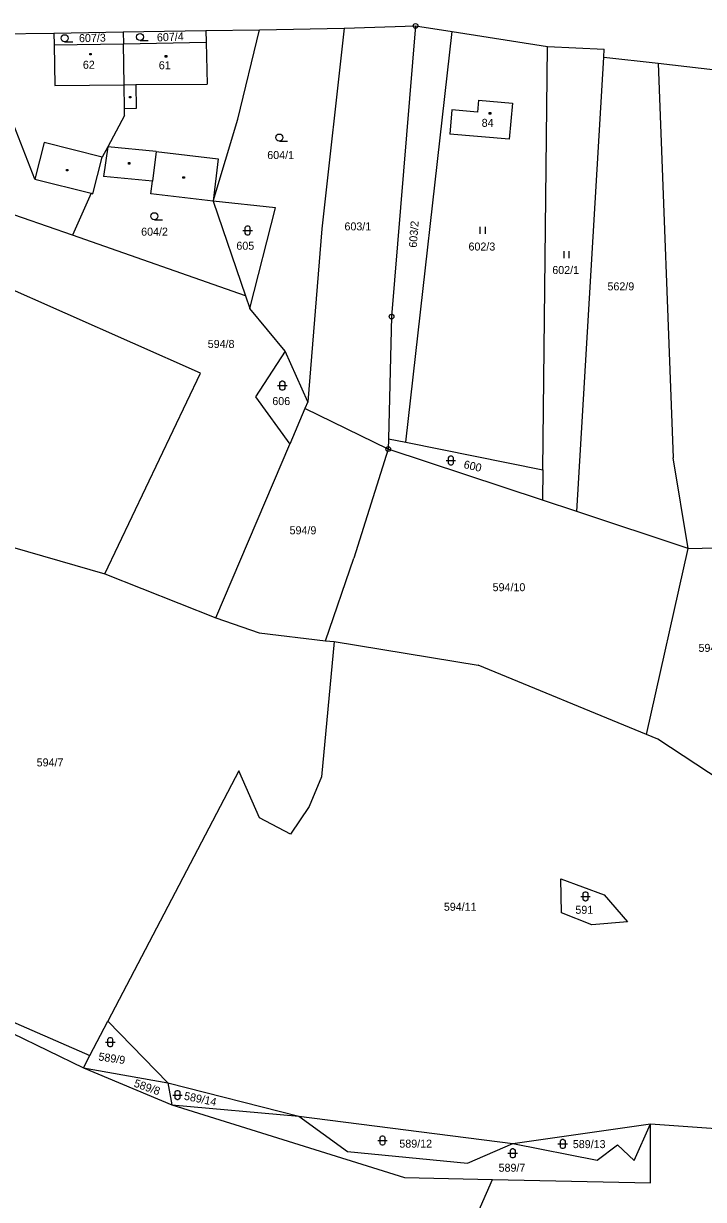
# Model space of a CAD drawing. Extents: x -791032 to -787751, y -1106872 to -1104403.
# Drawn here: x -789077.2 to -788932.6, y -1105471.5 to -1105221.6 of the extents above; entities that cross this region are included whole.
import ezdxf

# ---------------------------------------------------------------- set-up
doc = ezdxf.new("R2010")
doc.units = 0
for name, color, linetype in [('Vrstva 1', 7, 'Continuous'), ('Vrstva 14', 7, 'Continuous'), ('Vrstva 15', 7, 'Continuous'), ('Vrstva 2', 7, 'Continuous'), ('Vrstva 23', 7, 'Continuous'), ('Vrstva 25', 7, 'Continuous'), ('Vrstva 28', 7, 'Continuous')]:
    doc.layers.add(name, color=color, linetype=linetype)

msp = doc.modelspace()

# ---------------------------------------------------------------- linework, layer by layer
at = {"layer": 'Vrstva 1'}
for p, q in [((-789055.97, -1105223.43), (-789038.4, -1105223.14)), ((-789038.4, -1105223.14), (-789027.01, -1105222.95)), ((-789038.4, -1105223.14), (-789038.34, -1105225.61)), ((-789031.62, -1105241.98), (-789027.01, -1105222.95)), ((-789027.01, -1105222.95), (-789008.99, -1105222.66)), ((-789008.99, -1105222.66), (-789013.78, -1105265.28)), ((-789008.99, -1105222.66), (-788993.84, -1105222.14)), ((-788993.84, -1105222.14), (-788998.94, -1105283.9)), ((-788995.93, -1105310.61), (-788986.07, -1105223.35)), ((-788993.84, -1105222.14), (-788986.07, -1105223.35)), ((-788986.07, -1105223.35), (-788965.77, -1105226.5)), ((-789086.8, -1105223.93), (-789070.73, -1105223.67)), ((-789074.73, -1105254.68), (-789086.8, -1105223.93)), ((-789070.73, -1105223.67), (-789055.97, -1105223.43)), ((-789070.73, -1105223.67), (-789070.67, -1105226.2)), ((-789055.97, -1105223.43), (-789055.93, -1105225.93)), ((-789055.93, -1105225.93), (-789038.34, -1105225.61)), ((-789070.67, -1105226.2), (-789055.93, -1105225.93)), ((-789055.78, -1105234.64), (-789055.93, -1105225.93)), ((-788966.77, -1105316.48), (-788965.77, -1105226.5)), ((-788965.77, -1105226.5), (-788953.75, -1105227.08)), ((-788953.85, -1105228.78), (-788953.75, -1105227.08)), ((-788959.53, -1105325.34), (-788953.85, -1105228.78)), ((-788953.85, -1105228.78), (-788942.24, -1105230.09)), ((-788942.24, -1105230.09), (-788916.68, -1105232.99)), ((-788942.24, -1105230.09), (-788939.08, -1105313.94)), ((-789055.68, -1105239.76), (-789055.78, -1105234.64)), ((-788980.45, -1105237.95), (-788980.65, -1105240.44)), ((-788980.45, -1105237.95), (-788973.24, -1105238.59)), ((-789055.66, -1105241.15), (-789055.68, -1105239.76)), ((-788986.14, -1105240), (-788986.55, -1105245.18)), ((-788980.65, -1105240.44), (-788986.14, -1105240)), ((-788973.24, -1105238.59), (-788973.95, -1105246.19)), ((-789055.66, -1105241.15), (-789059.25, -1105247.81)), ((-789036.84, -1105259.37), (-789031.62, -1105241.98)), ((-788973.95, -1105246.19), (-788986.55, -1105245.18)), ((-789059.25, -1105247.81), (-789060.45, -1105250.04)), ((-789059.25, -1105247.81), (-789060.12, -1105254.11)), ((-789062.42, -1105257.8), (-789060.45, -1105250.04)), ((-789066.71, -1105266.61), (-789099.4, -1105255.27)), ((-789074.73, -1105254.68), (-789062.81, -1105257.7)), ((-789049.76, -1105255.16), (-789060.12, -1105254.11)), ((-789050.11, -1105257.8), (-789049.76, -1105255.16)), ((-789062.81, -1105257.7), (-789066.71, -1105266.61)), ((-789062.81, -1105257.7), (-789062.42, -1105257.8)), ((-789036.84, -1105259.37), (-789050.11, -1105257.8)), ((-789023.57, -1105260.83), (-789036.84, -1105259.37)), ((-789036.84, -1105259.37), (-789029.97, -1105279.46)), ((-789029.03, -1105282.2), (-789023.57, -1105260.83)), ((-789039.51, -1105295.94), (-789114.21, -1105262.89)), ((-789013.78, -1105265.28), (-789016.75, -1105302.03)), ((-789029.97, -1105279.46), (-789066.71, -1105266.61)), ((-789029.97, -1105279.46), (-789029.03, -1105282.2)), ((-789021.57, -1105291.22), (-789029.03, -1105282.2)), ((-788998.94, -1105283.9), (-788999.59, -1105309.87)), ((-789021.57, -1105291.22), (-789027.86, -1105300.92)), ((-789016.75, -1105302.03), (-789021.57, -1105291.22)), ((-789059.86, -1105338.55), (-789039.51, -1105295.94)), ((-789027.86, -1105300.92), (-789020.57, -1105311)), ((-789016.75, -1105302.03), (-789017.35, -1105303.43)), ((-789017.35, -1105303.43), (-789020.57, -1105311)), ((-788999.64, -1105312.04), (-789017.35, -1105303.43)), ((-788999.59, -1105309.87), (-788999.64, -1105312.04)), ((-788999.59, -1105309.87), (-788995.93, -1105310.61)), ((-788995.93, -1105310.61), (-788966.77, -1105316.48)), ((-789036.27, -1105347.9), (-789020.57, -1105311)), ((-788999.64, -1105312.04), (-789006.97, -1105335.19)), ((-788966.84, -1105322.92), (-788999.64, -1105312.04)), ((-788935.87, -1105333.19), (-788939.08, -1105313.94)), ((-788966.77, -1105316.48), (-788966.84, -1105322.92)), ((-788959.53, -1105325.34), (-788966.84, -1105322.92)), ((-788935.87, -1105333.19), (-788959.53, -1105325.34)), ((-789091.87, -1105329.34), (-789059.86, -1105338.55)), ((-788944.74, -1105372.67), (-788935.87, -1105333.19)), ((-788935.87, -1105333.19), (-788918.93, -1105332.67)), ((-789012.95, -1105352.75), (-789006.97, -1105335.19)), ((-789059.86, -1105338.55), (-789036.27, -1105347.9)), ((-789036.27, -1105347.9), (-789027.04, -1105351.11)), ((-789027.04, -1105351.11), (-789012.95, -1105352.75)), ((-789011.14, -1105352.96), (-789013.82, -1105381.68)), ((-789012.95, -1105352.75), (-789011.14, -1105352.96)), ((-789011.14, -1105352.96), (-788980.56, -1105357.96)), ((-788944.74, -1105372.67), (-788980.56, -1105357.96)), ((-788942.31, -1105373.67), (-788944.74, -1105372.67)), ((-788928.91, -1105382.54), (-788942.31, -1105373.67)), ((-789031.41, -1105380.38), (-789059.26, -1105433.59)), ((-789027, -1105390.37), (-789031.41, -1105380.38)), ((-789013.82, -1105381.68), (-789016.43, -1105387.95)), ((-789016.43, -1105387.95), (-789020.4, -1105393.85)), ((-789020.4, -1105393.85), (-789027, -1105390.37)), ((-788962.94, -1105403.36), (-788953.73, -1105406.76)), ((-788962.84, -1105410.54), (-788962.94, -1105403.36)), ((-788953.73, -1105406.76), (-788948.8, -1105412.45)), ((-788956.38, -1105413.14), (-788962.84, -1105410.54)), ((-788948.8, -1105412.45), (-788956.38, -1105413.14)), ((-789092.69, -1105427.98), (-789063.07, -1105440.87)), ((-789063.07, -1105440.87), (-789059.26, -1105433.59)), ((-789059.26, -1105433.59), (-789046.46, -1105446.71)), ((-789079.58, -1105436.15), (-789064.43, -1105443.48)), ((-789064.43, -1105443.48), (-789063.07, -1105440.87)), ((-789064.43, -1105443.48), (-789045.62, -1105451.38)), ((-789064.43, -1105443.48), (-789046.46, -1105446.71)), ((-789046.46, -1105446.71), (-789045.62, -1105451.38)), ((-789046.46, -1105446.71), (-789018.61, -1105453.78)), ((-789045.62, -1105451.38), (-788996.21, -1105466.8)), ((-789045.62, -1105451.38), (-789018.61, -1105453.78)), ((-789018.61, -1105453.78), (-789008.3, -1105461.27)), ((-789018.61, -1105453.78), (-788973.19, -1105459.55)), ((-788973.19, -1105459.55), (-788943.93, -1105455.42)), ((-788947.34, -1105463.15), (-788943.93, -1105455.42)), ((-788943.93, -1105455.42), (-788924.79, -1105456.74)), ((-788943.91, -1105467.9), (-788943.93, -1105455.42)), ((-788982.77, -1105463.78), (-788973.19, -1105459.55)), ((-788973.19, -1105459.55), (-788955.21, -1105463.09)), ((-788955.21, -1105463.09), (-788950.91, -1105459.82)), ((-788950.91, -1105459.82), (-788947.34, -1105463.15)), ((-789008.3, -1105461.27), (-788982.77, -1105463.78)), ((-788996.21, -1105466.8), (-788977.5, -1105467.19)), ((-788983.32, -1105480.53), (-788977.5, -1105467.19)), ((-788977.5, -1105467.19), (-788943.91, -1105467.9))]:
    msp.add_line(p, q, dxfattribs=at)
at = {"layer": 'Vrstva 2'}
for p, q in [((-789038.34, -1105225.61), (-789038.12, -1105234.5)), ((-789070.67, -1105226.2), (-789070.47, -1105234.79)), ((-789070.47, -1105234.79), (-789055.78, -1105234.64)), ((-789055.78, -1105234.64), (-789053.27, -1105234.59)), ((-789053.27, -1105234.59), (-789038.12, -1105234.5)), ((-789053.27, -1105234.59), (-789053.18, -1105239.71)), ((-789053.18, -1105239.71), (-789055.68, -1105239.76)), ((-789072.76, -1105246.92), (-789074.73, -1105254.68)), ((-789060.45, -1105250.04), (-789072.76, -1105246.92)), ((-789048.95, -1105248.85), (-789059.25, -1105247.81)), ((-789048.95, -1105248.85), (-789049.76, -1105255.16)), ((-789048.95, -1105248.85), (-789035.78, -1105250.4)), ((-789035.78, -1105250.4), (-789036.84, -1105259.37))]:
    msp.add_line(p, q, dxfattribs=at)
at = {"layer": 'Vrstva 23'}
for p, q in [((-789068.41, -1105225.52), (-789066.66, -1105225.52)), ((-789052.38, -1105225.25), (-789050.63, -1105225.25)), ((-789022.78, -1105246.62), (-789021.03, -1105246.62)), ((-789049.35, -1105263.33), (-789047.6, -1105263.33)), ((-789030.52, -1105265.6), (-789028.52, -1105265.6)), ((-789030.02, -1105265), (-789029.92, -1105264.8)), ((-789030.02, -1105266.2), (-789030.02, -1105265)), ((-789029.92, -1105264.8), (-789029.82, -1105264.7)), ((-789029.82, -1105264.7), (-789029.62, -1105264.6)), ((-789029.62, -1105264.6), (-789029.42, -1105264.6)), ((-789029.42, -1105264.6), (-789029.22, -1105264.7)), ((-789029.22, -1105264.7), (-789029.12, -1105264.8)), ((-789029.12, -1105264.8), (-789029.02, -1105265)), ((-789029.02, -1105265), (-789029.02, -1105266.2)), ((-788980.07, -1105266.34), (-788980.07, -1105264.84)), ((-788979.07, -1105264.84), (-788979.07, -1105266.34)), ((-789029.92, -1105266.4), (-789030.02, -1105266.2)), ((-789029.82, -1105266.5), (-789029.92, -1105266.4)), ((-789029.62, -1105266.6), (-789029.82, -1105266.5)), ((-789029.42, -1105266.6), (-789029.62, -1105266.6)), ((-789029.22, -1105266.5), (-789029.42, -1105266.6)), ((-789029.12, -1105266.4), (-789029.22, -1105266.5)), ((-789029.02, -1105266.2), (-789029.12, -1105266.4)), ((-788962.26, -1105271.47), (-788962.26, -1105269.97)), ((-788961.26, -1105269.97), (-788961.26, -1105271.47)), ((-789022.65, -1105297.96), (-789022.55, -1105297.76)), ((-789022.65, -1105299.16), (-789022.65, -1105297.96)), ((-789022.55, -1105297.76), (-789022.45, -1105297.66)), ((-789022.45, -1105297.66), (-789022.25, -1105297.56)), ((-789022.25, -1105297.56), (-789022.05, -1105297.56)), ((-789022.05, -1105297.56), (-789021.85, -1105297.66)), ((-789021.85, -1105297.66), (-789021.75, -1105297.76)), ((-789021.75, -1105297.76), (-789021.65, -1105297.96)), ((-789021.65, -1105297.96), (-789021.65, -1105299.16)), ((-789023.15, -1105298.56), (-789021.15, -1105298.56)), ((-789022.55, -1105299.36), (-789022.65, -1105299.16)), ((-789022.45, -1105299.46), (-789022.55, -1105299.36)), ((-789022.25, -1105299.56), (-789022.45, -1105299.46)), ((-789022.05, -1105299.56), (-789022.25, -1105299.56)), ((-789021.85, -1105299.46), (-789022.05, -1105299.56)), ((-789021.75, -1105299.36), (-789021.85, -1105299.46)), ((-789021.65, -1105299.16), (-789021.75, -1105299.36)), ((-788987.32, -1105314.48), (-788985.32, -1105314.48)), ((-788986.82, -1105313.88), (-788986.72, -1105313.68)), ((-788986.82, -1105315.08), (-788986.82, -1105313.88)), ((-788986.72, -1105315.28), (-788986.82, -1105315.08)), ((-788986.72, -1105313.68), (-788986.62, -1105313.58)), ((-788986.62, -1105315.38), (-788986.72, -1105315.28)), ((-788986.62, -1105313.58), (-788986.42, -1105313.48)), ((-788986.42, -1105315.48), (-788986.62, -1105315.38)), ((-788986.42, -1105313.48), (-788986.22, -1105313.48)), ((-788986.22, -1105315.48), (-788986.42, -1105315.48)), ((-788986.22, -1105313.48), (-788986.02, -1105313.58)), ((-788986.02, -1105315.38), (-788986.22, -1105315.48)), ((-788986.02, -1105313.58), (-788985.92, -1105313.68)), ((-788985.92, -1105315.28), (-788986.02, -1105315.38)), ((-788985.92, -1105313.68), (-788985.82, -1105313.88)), ((-788985.82, -1105315.08), (-788985.92, -1105315.28)), ((-788985.82, -1105313.88), (-788985.82, -1105315.08)), ((-788958.72, -1105407.08), (-788956.72, -1105407.08)), ((-788958.22, -1105406.48), (-788958.12, -1105406.28)), ((-788958.22, -1105407.68), (-788958.22, -1105406.48)), ((-788958.12, -1105407.88), (-788958.22, -1105407.68)), ((-788958.12, -1105406.28), (-788958.02, -1105406.18)), ((-788958.02, -1105407.98), (-788958.12, -1105407.88)), ((-788958.02, -1105406.18), (-788957.82, -1105406.08)), ((-788957.82, -1105408.08), (-788958.02, -1105407.98)), ((-788957.82, -1105406.08), (-788957.62, -1105406.08)), ((-788957.62, -1105408.08), (-788957.82, -1105408.08)), ((-788957.62, -1105406.08), (-788957.42, -1105406.18)), ((-788957.42, -1105407.98), (-788957.62, -1105408.08)), ((-788957.42, -1105406.18), (-788957.32, -1105406.28)), ((-788957.32, -1105407.88), (-788957.42, -1105407.98)), ((-788957.32, -1105406.28), (-788957.22, -1105406.48)), ((-788957.22, -1105407.68), (-788957.32, -1105407.88)), ((-788957.22, -1105406.48), (-788957.22, -1105407.68)), ((-789059.71, -1105438.03), (-789057.71, -1105438.03)), ((-789059.21, -1105437.43), (-789059.11, -1105437.23)), ((-789059.21, -1105438.63), (-789059.21, -1105437.43)), ((-789059.11, -1105437.23), (-789059.01, -1105437.13)), ((-789059.01, -1105437.13), (-789058.81, -1105437.03)), ((-789058.81, -1105437.03), (-789058.61, -1105437.03)), ((-789058.61, -1105437.03), (-789058.41, -1105437.13)), ((-789058.41, -1105437.13), (-789058.31, -1105437.23)), ((-789058.31, -1105437.23), (-789058.21, -1105437.43)), ((-789058.21, -1105437.43), (-789058.21, -1105438.63)), ((-789059.11, -1105438.83), (-789059.21, -1105438.63)), ((-789059.01, -1105438.93), (-789059.11, -1105438.83)), ((-789058.81, -1105439.03), (-789059.01, -1105438.93)), ((-789058.61, -1105439.03), (-789058.81, -1105439.03)), ((-789058.41, -1105438.93), (-789058.61, -1105439.03)), ((-789058.31, -1105438.83), (-789058.41, -1105438.93)), ((-789058.21, -1105438.63), (-789058.31, -1105438.83)), ((-789045.43, -1105449.28), (-789043.43, -1105449.28)), ((-789044.93, -1105448.68), (-789044.83, -1105448.48)), ((-789044.93, -1105449.88), (-789044.93, -1105448.68)), ((-789044.83, -1105450.08), (-789044.93, -1105449.88)), ((-789044.83, -1105448.48), (-789044.73, -1105448.38)), ((-789044.73, -1105450.18), (-789044.83, -1105450.08)), ((-789044.73, -1105448.38), (-789044.53, -1105448.28)), ((-789044.53, -1105450.28), (-789044.73, -1105450.18)), ((-789044.53, -1105448.28), (-789044.33, -1105448.28)), ((-789044.33, -1105450.28), (-789044.53, -1105450.28)), ((-789044.33, -1105448.28), (-789044.13, -1105448.38)), ((-789044.13, -1105450.18), (-789044.33, -1105450.28)), ((-789044.13, -1105448.38), (-789044.03, -1105448.48)), ((-789044.03, -1105450.08), (-789044.13, -1105450.18)), ((-789044.03, -1105448.48), (-789043.93, -1105448.68)), ((-789043.93, -1105449.88), (-789044.03, -1105450.08)), ((-789043.93, -1105448.68), (-789043.93, -1105449.88)), ((-789001.36, -1105458.34), (-789001.26, -1105458.14)), ((-789001.26, -1105458.14), (-789001.16, -1105458.04)), ((-789001.16, -1105458.04), (-789000.96, -1105457.94)), ((-789000.96, -1105457.94), (-789000.76, -1105457.94)), ((-789000.76, -1105457.94), (-789000.56, -1105458.04)), ((-789000.56, -1105458.04), (-789000.46, -1105458.14)), ((-789000.46, -1105458.14), (-789000.36, -1105458.34)), ((-789001.86, -1105458.94), (-788999.86, -1105458.94)), ((-789001.36, -1105459.54), (-789001.36, -1105458.34)), ((-789001.26, -1105459.74), (-789001.36, -1105459.54)), ((-789001.16, -1105459.84), (-789001.26, -1105459.74)), ((-789000.96, -1105459.94), (-789001.16, -1105459.84)), ((-789000.76, -1105459.94), (-789000.96, -1105459.94)), ((-789000.56, -1105459.84), (-789000.76, -1105459.94)), ((-789000.46, -1105459.74), (-789000.56, -1105459.84)), ((-789000.36, -1105459.54), (-789000.46, -1105459.74)), ((-789000.36, -1105458.34), (-789000.36, -1105459.54)), ((-788973.59, -1105460.85), (-788973.49, -1105460.75)), ((-788973.49, -1105460.75), (-788973.29, -1105460.65)), ((-788973.29, -1105460.65), (-788973.09, -1105460.65)), ((-788973.09, -1105460.65), (-788972.89, -1105460.75)), ((-788972.89, -1105460.75), (-788972.79, -1105460.85)), ((-788963.56, -1105459.66), (-788961.56, -1105459.66)), ((-788963.06, -1105459.06), (-788962.96, -1105458.86)), ((-788963.06, -1105460.26), (-788963.06, -1105459.06)), ((-788962.96, -1105460.46), (-788963.06, -1105460.26)), ((-788962.96, -1105458.86), (-788962.86, -1105458.76)), ((-788962.86, -1105460.56), (-788962.96, -1105460.46)), ((-788962.86, -1105458.76), (-788962.66, -1105458.66)), ((-788962.66, -1105460.66), (-788962.86, -1105460.56)), ((-788962.66, -1105458.66), (-788962.46, -1105458.66)), ((-788962.46, -1105460.66), (-788962.66, -1105460.66)), ((-788962.46, -1105458.66), (-788962.26, -1105458.76)), ((-788962.26, -1105460.56), (-788962.46, -1105460.66)), ((-788962.26, -1105458.76), (-788962.16, -1105458.86)), ((-788962.16, -1105460.46), (-788962.26, -1105460.56)), ((-788962.16, -1105458.86), (-788962.06, -1105459.06)), ((-788962.06, -1105460.26), (-788962.16, -1105460.46)), ((-788962.06, -1105459.06), (-788962.06, -1105460.26)), ((-788974.19, -1105461.65), (-788972.19, -1105461.65)), ((-788973.69, -1105461.05), (-788973.59, -1105460.85)), ((-788973.69, -1105462.25), (-788973.69, -1105461.05)), ((-788973.59, -1105462.45), (-788973.69, -1105462.25)), ((-788973.49, -1105462.55), (-788973.59, -1105462.45)), ((-788973.29, -1105462.65), (-788973.49, -1105462.55)), ((-788973.09, -1105462.65), (-788973.29, -1105462.65)), ((-788972.89, -1105462.55), (-788973.09, -1105462.65)), ((-788972.79, -1105462.45), (-788972.89, -1105462.55)), ((-788972.79, -1105460.85), (-788972.69, -1105461.05)), ((-788972.69, -1105462.25), (-788972.79, -1105462.45)), ((-788972.69, -1105461.05), (-788972.69, -1105462.25))]:
    msp.add_line(p, q, dxfattribs=at)
for centre in [(-789068.41, -1105224.77), (-789052.38, -1105224.5), (-789022.78, -1105245.87), (-789049.35, -1105262.58)]:
    msp.add_circle(centre, 0.75, dxfattribs=at)
at = {"layer": 'Vrstva 25'}
for p, q in [((-789063.05, -1105228.01), (-789062.75, -1105228.01)), ((-789063.05, -1105228.31), (-789063.05, -1105228.01)), ((-789062.75, -1105228.31), (-789063.05, -1105228.31)), ((-789062.75, -1105228.01), (-789062.75, -1105228.31)), ((-789047.02, -1105228.46), (-789046.72, -1105228.46)), ((-789047.02, -1105228.76), (-789047.02, -1105228.46)), ((-789046.72, -1105228.76), (-789047.02, -1105228.76)), ((-789046.72, -1105228.46), (-789046.72, -1105228.76)), ((-789054.66, -1105237.16), (-789054.36, -1105237.16)), ((-789054.66, -1105237.46), (-789054.66, -1105237.16)), ((-789054.36, -1105237.46), (-789054.66, -1105237.46)), ((-789054.36, -1105237.16), (-789054.36, -1105237.46)), ((-788978.16, -1105240.57), (-788977.86, -1105240.57)), ((-788978.16, -1105240.87), (-788978.16, -1105240.57)), ((-788977.86, -1105240.87), (-788978.16, -1105240.87)), ((-788977.86, -1105240.57), (-788977.86, -1105240.87)), ((-789068.04, -1105252.62), (-789067.74, -1105252.62)), ((-789068.04, -1105252.92), (-789068.04, -1105252.62)), ((-789067.74, -1105252.92), (-789068.04, -1105252.92)), ((-789067.74, -1105252.62), (-789067.74, -1105252.92)), ((-789054.84, -1105251.19), (-789054.54, -1105251.19)), ((-789054.84, -1105251.49), (-789054.84, -1105251.19)), ((-789054.54, -1105251.49), (-789054.84, -1105251.49)), ((-789054.54, -1105251.19), (-789054.54, -1105251.49)), ((-789043.27, -1105254.2), (-789042.97, -1105254.2)), ((-789043.27, -1105254.5), (-789043.27, -1105254.2)), ((-789042.97, -1105254.5), (-789043.27, -1105254.5)), ((-789042.97, -1105254.2), (-789042.97, -1105254.5))]:
    msp.add_line(p, q, dxfattribs=at)
at = {"layer": 'Vrstva 28'}
for centre, radius in [((-788993.84, -1105222.14), 0.5), ((-788993.84, -1105222.14), 0.01), ((-788998.94, -1105283.9), 0.5), ((-788998.94, -1105283.9), 0.01), ((-788999.64, -1105312.04), 0.5), ((-788999.64, -1105312.04), 0.01)]:
    msp.add_circle(centre, radius, dxfattribs=at)

# ---------------------------------------------------------------- texts
at = {"layer": 'Vrstva 14'}
for s, rotation, p in [('607/3', 1.24533, (-789065.345, -1105225.607)), ('607/4', 2.18457, (-789048.769, -1105225.444)), ('603/2', 85.74309, (-788993.579, -1105269.309)), ('600', 346.86594, (-788983.727, -1105316.056)), ('589/9', 351.75123, (-789061.31, -1105441.904)), ('589/8', 340.44138, (-789053.844, -1105447.446)), ('589/14', 348.48765, (-789043.144, -1105450.238))]:
    msp.add_text(s, height=1.7, rotation=rotation, dxfattribs=at).set_placement(p)
for s, p in [('604/1', (-789025.348, -1105250.43)), ('604/2', (-789052.155, -1105266.71)), ('603/1', (-789008.942, -1105265.59)), ('605', (-789031.912, -1105269.7)), ('602/3', (-788982.579, -1105269.87)), ('602/1', (-788964.772, -1105274.86)), ('562/9', (-788953.046, -1105278.33)), ('594/8', (-789038.002, -1105290.56)), ('606', (-789024.276, -1105302.7)), ('594/9', (-789020.602, -1105330.15)), ('594/10', (-788977.454, -1105342.24)), ('594/5', (-788933.698, -1105355.13)), ('594/7', (-789074.359, -1105379.46)), ('594/11', (-788987.818, -1105410.13)), ('591', (-788959.866, -1105410.77)), ('589/12', (-788997.279, -1105460.45)), ('589/13', (-788960.409, -1105460.55)), ('589/7', (-788976.183, -1105465.57))]:
    msp.add_text(s, height=1.7, dxfattribs=at).set_placement(p)
at = {"layer": 'Vrstva 15'}
for s, p in [('62', (-789064.537, -1105231.25)), ('61', (-789048.4, -1105231.36)), ('84', (-788979.782, -1105243.59))]:
    msp.add_text(s, height=1.7, dxfattribs=at).set_placement(p)

doc.saveas('drawing.dxf')
